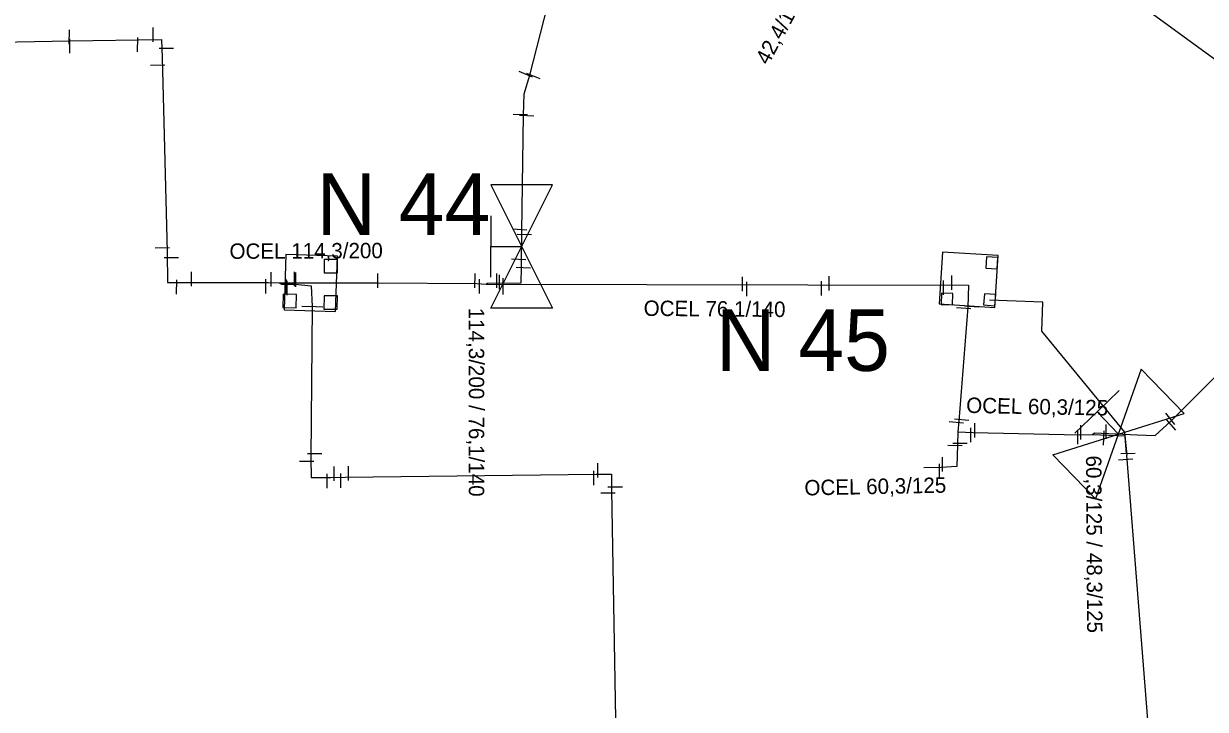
# Model space of a CAD drawing. Extents: x -642943 to -623314, y -1138561 to -1113539.
# Drawn here: x -641619.1 to -641561.5, y -1115267.7 to -1115234.3 of the extents above; entities that cross this region are included whole.
import ezdxf

# ---------------------------------------------------------------- set-up
doc = ezdxf.new("R2010")
doc.units = 0
for name, color, linetype in [('horkovod armatury', 7, 'Continuous'), ('horkovod dimenze', 7, 'Continuous'), ('horkovod předisol', 7, 'Continuous'), ('horkovod sváry', 7, 'Continuous'), ('horkovod trasa', 7, 'Continuous'), ('horkovod zrušený', 7, 'Continuous'), ('horkovod číslo šachty', 7, 'Continuous'), ('horkovod šachty', 7, 'Continuous')]:
    doc.layers.add(name, color=color, linetype=linetype)

# ---------------------------------------------------------------- blocks, each defined once
blk = doc.blocks.new('SPH')
at = {"layer": 'horkovod sváry'}
blk.add_line((0, -0.035), (0, 0.035), dxfattribs=at)
blk = doc.blocks.new('SPH_1')
at = {"layer": 'horkovod sváry'}
blk.add_line((0.0001, -0.035), (-0.0001, 0.035), dxfattribs=at)
blk = doc.blocks.new('SPH_2')
at = {"layer": 'horkovod sváry'}
blk.add_line((-0.0001, -0.0349), (0.0001, 0.0349), dxfattribs=at)
blk = doc.blocks.new('POINT_DISPLAY')
blk.add_line((0, 0), (0, 0))
blk = doc.blocks.new('SCH_01_13')
at = {"layer": 'horkovod armatury'}
for p, q in [((10, 5), (-10, -5)), ((-10, -5), (-10, 5)), ((-10, 5), (10, -5)), ((-5, 5), (0, 5)), ((0, 5), (0, 0)), ((5, 5), (0, 5)), ((10, -5), (10, 5))]:
    blk.add_line(p, q, dxfattribs=at)
blk = doc.blocks.new('SCH_01_10')
at = {"layer": 'horkovod armatury'}
for p, q in [((10, 5), (-10, -5)), ((-10, -5), (-10, 5)), ((-10, 5), (10, -5)), ((-5, 5), (0, 5)), ((0, 5), (0, 0)), ((5, 5), (0, 5)), ((10, -5), (10, 5))]:
    blk.add_line(p, q, dxfattribs=at)

msp = doc.modelspace()

# ---------------------------------------------------------------- linework, layer by layer
at = {"layer": 'horkovod předisol'}
msp.add_line((-641596.589, -1115246.991), (-641573.075, -1115247.038), dxfattribs=at)
for points in [[(-641596.589, -1115246.991), (-641596.515, -1115246.94), (-641594.883, -1115246.929), (-641594.871, -1115246.178), (-641594.84, -1115244.416), (-641594.765, -1115238.748), (-641594.731, -1115237.709), (-641594.459, -1115236.807), (-641592.901, -1115230.709), (-641590.614, -1115222.271), (-641590.479, -1115221.744)], [(-641645.447, -1115235.609), (-641642.447, -1115235.609), (-641640.936, -1115235.572), (-641628.951, -1115235.355), (-641616.871, -1115235.136), (-641612.407, -1115235.076), (-641612.378, -1115235.95), (-641612.13, -1115245.417), (-641612.124, -1115246.899), (-641611.215, -1115246.905), (-641607.195, -1115246.915), (-641606.679, -1115246.916)], [(-641567.044, -1115254.309), (-641566.933, -1115254.232), (-641564.862, -1115254.333), (-641563.975, -1115254.352), (-641563.212, -1115253.667), (-641558.434, -1115248.889), (-641553.01, -1115243.008), (-641552.302, -1115242.398), (-641551.362, -1115242.328), (-641549.937, -1115242.386), (-641549.32, -1115242.447)], [(-641606.679, -1115246.916), (-641606.553, -1115246.994), (-641605.891, -1115246.989), (-641605.111, -1115247.073), (-641605.072, -1115248.084)], [(-641606.679, -1115246.916), (-641601.869, -1115246.93), (-641597.035, -1115246.952), (-641596.589, -1115246.991)], [(-641573.075, -1115247.038), (-641573.111, -1115248.109), (-641573.546, -1115253.664), (-641573.6, -1115254.185)], [(-641605.072, -1115248.084), (-641605.138, -1115255.452), (-641605.11, -1115256.402), (-641604.16, -1115256.402), (-641603.455, -1115256.383), (-641591.233, -1115256.248), (-641590.481, -1115256.24), (-641590.472, -1115257.029), (-641590.272, -1115269.093)], [(-641573.6, -1115254.185), (-641573.614, -1115254.818), (-641573.643, -1115255.877), (-641574.412, -1115255.916), (-641575.262, -1115255.929)], [(-641573.6, -1115254.185), (-641572.854, -1115254.214), (-641567.688, -1115254.322), (-641567.044, -1115254.309)], [(-641567.044, -1115254.309), (-641565.457, -1115254.372), (-641565.37, -1115255.324)], [(-641519.572, -1115305.8), (-641522.093, -1115305.688), (-641522.262, -1115298.676), (-641522.474, -1115289.482), (-641529.798, -1115289.89), (-641530.859, -1115276.623), (-641546.873, -1115277.71), (-641563.521, -1115278.443), (-641565.37, -1115255.324)]]:
    msp.add_lwpolyline(points, dxfattribs=at)
at = {"layer": 'horkovod trasa'}
msp.add_line((-641596.589, -1115246.991), (-641573.075, -1115247.038), dxfattribs=at)
for points in [[(-641596.589, -1115246.991), (-641596.515, -1115246.94), (-641594.883, -1115246.929), (-641594.871, -1115246.178), (-641594.84, -1115244.416), (-641594.765, -1115238.748), (-641594.731, -1115237.709), (-641594.459, -1115236.807), (-641592.901, -1115230.709), (-641590.614, -1115222.271), (-641590.479, -1115221.744)], [(-641645.447, -1115235.609), (-641642.447, -1115235.609), (-641640.936, -1115235.572), (-641628.951, -1115235.355), (-641616.871, -1115235.136), (-641612.407, -1115235.076), (-641612.378, -1115235.95), (-641612.13, -1115245.417), (-641612.124, -1115246.899), (-641611.215, -1115246.905), (-641607.195, -1115246.915), (-641606.679, -1115246.916)], [(-641567.044, -1115254.309), (-641566.933, -1115254.232), (-641564.862, -1115254.333), (-641563.975, -1115254.352), (-641563.212, -1115253.667), (-641558.434, -1115248.889), (-641553.01, -1115243.008), (-641552.302, -1115242.398), (-641551.362, -1115242.328), (-641549.937, -1115242.386), (-641549.32, -1115242.447)], [(-641606.679, -1115246.916), (-641606.553, -1115246.994), (-641605.891, -1115246.989), (-641605.111, -1115247.073), (-641605.072, -1115248.084)], [(-641606.679, -1115246.916), (-641601.869, -1115246.93), (-641597.035, -1115246.952), (-641596.589, -1115246.991)], [(-641573.075, -1115247.038), (-641573.111, -1115248.109), (-641573.546, -1115253.664), (-641573.6, -1115254.185)], [(-641605.072, -1115248.084), (-641605.138, -1115255.452), (-641605.11, -1115256.402), (-641604.16, -1115256.402), (-641603.455, -1115256.383), (-641591.233, -1115256.248), (-641590.481, -1115256.24), (-641590.472, -1115257.029), (-641590.272, -1115269.093)], [(-641573.6, -1115254.185), (-641573.614, -1115254.818), (-641573.643, -1115255.877), (-641574.412, -1115255.916), (-641575.262, -1115255.929)], [(-641573.6, -1115254.185), (-641572.854, -1115254.214), (-641567.688, -1115254.322), (-641567.044, -1115254.309)], [(-641567.044, -1115254.309), (-641565.457, -1115254.372), (-641565.37, -1115255.324)], [(-641519.572, -1115305.8), (-641522.093, -1115305.688), (-641522.262, -1115298.676), (-641522.474, -1115289.482), (-641529.798, -1115289.89), (-641530.859, -1115276.623), (-641546.873, -1115277.71), (-641563.521, -1115278.443), (-641565.37, -1115255.324)]]:
    msp.add_lwpolyline(points, dxfattribs=at)
at = {"layer": 'horkovod zrušený'}
for p, q in [((-641569.016, -1115230.241), (-641552.837, -1115242.03)), ((-641569.459, -1115247.873), (-641572.054, -1115247.77))]:
    msp.add_line(p, q, dxfattribs=at)
msp.add_lwpolyline([(-641565.376, -1115255.25), (-641565.461, -1115254.19), (-641569.513, -1115249.27), (-641569.459, -1115247.873)], dxfattribs=at)
at = {"layer": 'horkovod šachty'}
for p, q in [((-641604.479, -1115245.78), (-641604.479, -1115246.43)), ((-641603.829, -1115245.78), (-641604.479, -1115245.78)), ((-641603.829, -1115246.43), (-641603.829, -1115245.78)), ((-641572.203, -1115245.664), (-641572.235, -1115246.213)), ((-641571.653, -1115245.696), (-641572.203, -1115245.664)), ((-641571.686, -1115246.245), (-641571.653, -1115245.696)), ((-641604.479, -1115246.43), (-641603.829, -1115246.43)), ((-641572.235, -1115246.213), (-641571.686, -1115246.245)), ((-641606.473, -1115247.469), (-641606.5, -1115248.119)), ((-641605.823, -1115247.496), (-641606.473, -1115247.469)), ((-641605.85, -1115248.147), (-641605.823, -1115247.496)), ((-641604.487, -1115247.556), (-641604.492, -1115248.208)), ((-641603.835, -1115247.562), (-641604.487, -1115247.556)), ((-641603.841, -1115248.213), (-641603.835, -1115247.562)), ((-641574.391, -1115247.422), (-641574.407, -1115247.971)), ((-641573.841, -1115247.438), (-641574.391, -1115247.422)), ((-641573.858, -1115247.988), (-641573.841, -1115247.438)), ((-641572.304, -1115247.451), (-641572.344, -1115248)), ((-641571.755, -1115247.492), (-641572.304, -1115247.451)), ((-641571.796, -1115248.04), (-641571.755, -1115247.492)), ((-641606.5, -1115248.119), (-641605.85, -1115248.147)), ((-641604.492, -1115248.208), (-641603.841, -1115248.213)), ((-641574.407, -1115247.971), (-641573.858, -1115247.988)), ((-641572.344, -1115248), (-641571.796, -1115248.04))]:
    msp.add_line(p, q, dxfattribs=at)
for points in [[(-641571.794, -1115248.122), (-641571.633, -1115245.587), (-641574.348, -1115245.43), (-641574.508, -1115247.94), (-641571.794, -1115248.122)], [(-641603.936, -1115248.314), (-641603.831, -1115245.626), (-641606.349, -1115245.545), (-641606.435, -1115248.234), (-641603.936, -1115248.314)]]:
    msp.add_lwpolyline(points, dxfattribs=at)

# ---------------------------------------------------------------- block references
at = {"layer": 'horkovod armatury'}
for name, p, xscale, yscale, rotation in [('SCH_01_10', (-641594.858, -1115245.154), 0.2999795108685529, 0.2999795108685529, 90), ('SCH_01_13', (-641565.775, -1115254.29), 0.29998097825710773, 0.2999809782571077, 43.99837472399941)]:
    msp.add_blockref(name, p, dxfattribs=dict(at, xscale=xscale, yscale=yscale, rotation=rotation))
at = {"layer": 'horkovod sváry', "xscale": 10, "yscale": 10}
for name, p in [('SPH_2', (-641616.9, -1115234.941)), ('SPH_2', (-641616.88, -1115235.381)), ('SPH_2', (-641613.57, -1115235.321)), ('SPH_2', (-641612.82, -1115234.841)), ('SPH_2', (-641610.94, -1115246.731)), ('SPH_2', (-641607.07, -1115246.751)), ('SPH_2', (-641605.93, -1115246.731)), ('SPH_2', (-641605.86, -1115246.771)), ('SPH_2', (-641601.87, -1115246.811)), ('SPH_2', (-641597.13, -1115246.821)), ('SPH_2', (-641596.06, -1115246.821)), ('SPH_2', (-641595.93, -1115246.881)), ('SPH_2', (-641573.89, -1115246.921)), ('SPH_2', (-641611.67, -1115247.121)), ('SPH_2', (-641607.32, -1115247.101)), ('SPH_2', (-641606.32, -1115247.111)), ('SPH_2', (-641606.28, -1115247.171)), ('SPH_2', (-641596.91, -1115247.091)), ('SPH_2', (-641595.76, -1115247.051)), ('SPH_2', (-641595.76, -1115247.141)), ('SPH_2', (-641584.1, -1115246.981)), ('SPH_2', (-641583.88, -1115247.221)), ('SPH_2', (-641580.25, -1115247.191)), ('SPH_2', (-641579.87, -1115246.941)), ('SPH_2', (-641574.3, -1115247.161)), ('SPH_2', (-641572.96, -1115254.341)), ('SPH_2', (-641572.77, -1115254.101)), ('SPH_2', (-641567.61, -1115254.201)), ('SPH_2', (-641566.37, -1115254.171)), ('SPH_2', (-641567.75, -1115254.441)), ('SPH_1', (-641591.14, -1115256.06)), ('SPH_2', (-641574.49, -1115256.081)), ('SPH_2', (-641574.35, -1115255.761)), ('SPH_1', (-641604.33, -1115256.57)), ('SPH_1', (-641603.99, -1115256.22)), ('SPH_1', (-641603.67, -1115256.56)), ('SPH_1', (-641603.29, -1115256.2)), ('SPH_1', (-641591.34, -1115256.43))]:
    msp.add_blockref(name, p, dxfattribs=at)
at = {"layer": 'horkovod sváry'}
for name, p, xscale, yscale, rotation in [('SPH_2', (-641612.17, -1115235.491), 10.00000395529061, 10.00000395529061, -89.94904031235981), ('SPH_2', (-641612.6, -1115236.311), 9.999995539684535, 9.999995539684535, -89.5405571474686), ('SPH_2', (-641594.65, -1115236.761), 9.999991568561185, 9.999991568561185, 67.10304677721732), ('SPH_2', (-641594.28, -1115236.851), 10.000009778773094, 10.000009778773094, 67.94303994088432), ('SPH_2', (-641594.92, -1115238.721), 10.000016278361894, 10.000016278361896, -91.12438541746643), ('SPH_2', (-641594.62, -1115238.771), 9.99998464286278, 9.99998464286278, -91.79749417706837), ('SPH_2', (-641594.95, -1115244.311), 9.999986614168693, 9.999986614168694, -93.81840525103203), ('SPH_2', (-641594.73, -1115244.561), 10.000016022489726, 10.000016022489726, -91.99636681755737), ('SPH_2', (-641612.37, -1115245.211), 9.99998630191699, 9.999986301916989, -88.66024959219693), ('SPH_2', (-641611.93, -1115245.691), 9.99998133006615, 9.999981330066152, -90.66809540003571), ('SPH_1', (-641595, -1115245.771), 10.000006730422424, 10.000006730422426, -92.51677606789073), ('SPH_1', (-641594.77, -1115246.181), 9.999979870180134, 9.999979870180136, -92.47031471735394), ('SPH_2', (-641605.22, -1115248.071), 9.999992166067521, 9.99999216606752, -91.5623364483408), ('SPH_2', (-641604.9, -1115248.081), 9.999997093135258, 9.999997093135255, -92.00090904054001), ('SPH_2', (-641573.31, -1115248.171), 10.00000747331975, 10.000007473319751, 85.82026944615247), ('SPH_2', (-641572.92, -1115248.091), 9.999999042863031, 9.999999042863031, 86.19256276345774), ('SPH_2', (-641563.25, -1115253.551), 10.00000514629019, 10.00000514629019, 39.157287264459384), ('SPH_2', (-641573.67, -1115253.721), 10.00000003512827, 10.000000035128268, 84.55218049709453), ('SPH_2', (-641573.41, -1115253.591), 10.000022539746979, 10.00002253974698, 85.21491045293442), ('SPH_2', (-641563.2, -1115253.841), 10.000025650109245, 10.000025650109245, 41.10269747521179), ('SPH_2', (-641566.481, -1115254.487), 9.999999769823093, 9.999999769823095, -2.1910007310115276), ('SPH_2', (-641573.73, -1115254.861), 9.999991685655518, 9.99999168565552, 88.88281692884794), ('SPH_2', (-641573.5, -1115254.751), 10.000001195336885, 10.000001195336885, 90.0280144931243), ('SPH_2', (-641565.3, -1115255.231), 10.000017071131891, 10.000017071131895, -88.27458286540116), ('SPH', (-641605.34, -1115255.61), 9.999982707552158, 9.99998270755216, -91.086762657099), ('SPH', (-641604.94, -1115255.24), 9.999990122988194, 9.999990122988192, -89.61739881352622), ('SPH_1', (-641565.42, -1115255.521), 9.999978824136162, 9.99997882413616, -87.3854681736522), ('SPH', (-641590.3, -1115256.86), 10.000008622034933, 10.000008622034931, -89.92476111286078), ('SPH', (-641590.65, -1115257.15), 10.000014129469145, 10.000014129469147, -90.09631641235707)]:
    msp.add_blockref(name, p, dxfattribs=dict(at, xscale=xscale, yscale=yscale, rotation=rotation))
at = {"layer": 'horkovod šachty'}
for p in [(-641571.939, -1115245.95), (-641604.149, -1115246.1), (-641574.119, -1115247.7), (-641606.157, -1115247.813), (-641604.169, -1115247.88), (-641572.046, -1115247.751)]:
    msp.add_blockref('POINT_DISPLAY', p, dxfattribs=at)

# ---------------------------------------------------------------- texts
at = {"layer": 'horkovod dimenze'}
for s, height, rotation, p in [('42,4/125 / 33,7/110', 0.75, 61.51641, (-641582.841, -1115236.354)), ('OCEL 114,3/200', 0.75, 0.26343, (-641609.093, -1115245.757)), ('114,3/200 / 76,1/140', 0.75, 270, (-641597.433, -1115248.135)), ('OCEL 76,1/140', 0.75, 359.51569, (-641588.914, -1115248.532)), ('OCEL 60,3/125', 0.75, 358.88976, (-641573.197, -1115253.257)), ('60,3/125 / 48,3/125', 0.75, 270.37248, (-641567.354, -1115255.338)), ('OCEL 60,3/125', 0.74999, 1.15379, (-641581.069, -1115257.283))]:
    msp.add_text(s, height=height, rotation=rotation, dxfattribs=at).set_placement(p)
at = {"layer": 'horkovod číslo šachty'}
for s, p in [('N 44', (-641604.857, -1115244.593)), ('N 45', (-641585.382, -1115251.214))]:
    msp.add_text(s, height=3, dxfattribs=at).set_placement(p)

doc.saveas('drawing.dxf')
